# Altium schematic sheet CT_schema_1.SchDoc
size 515 x 463 mm
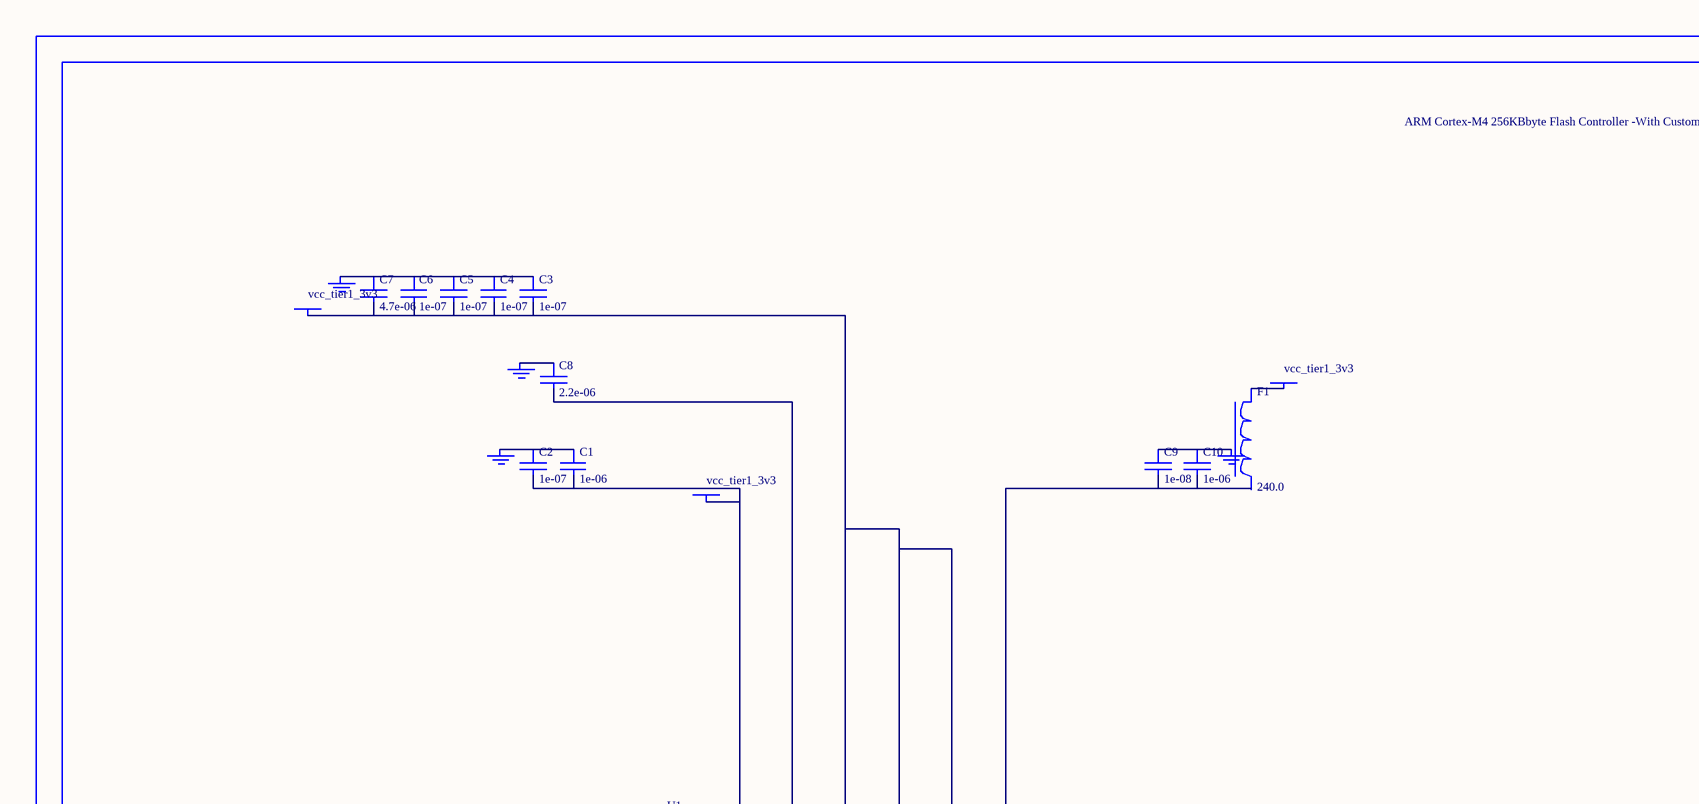
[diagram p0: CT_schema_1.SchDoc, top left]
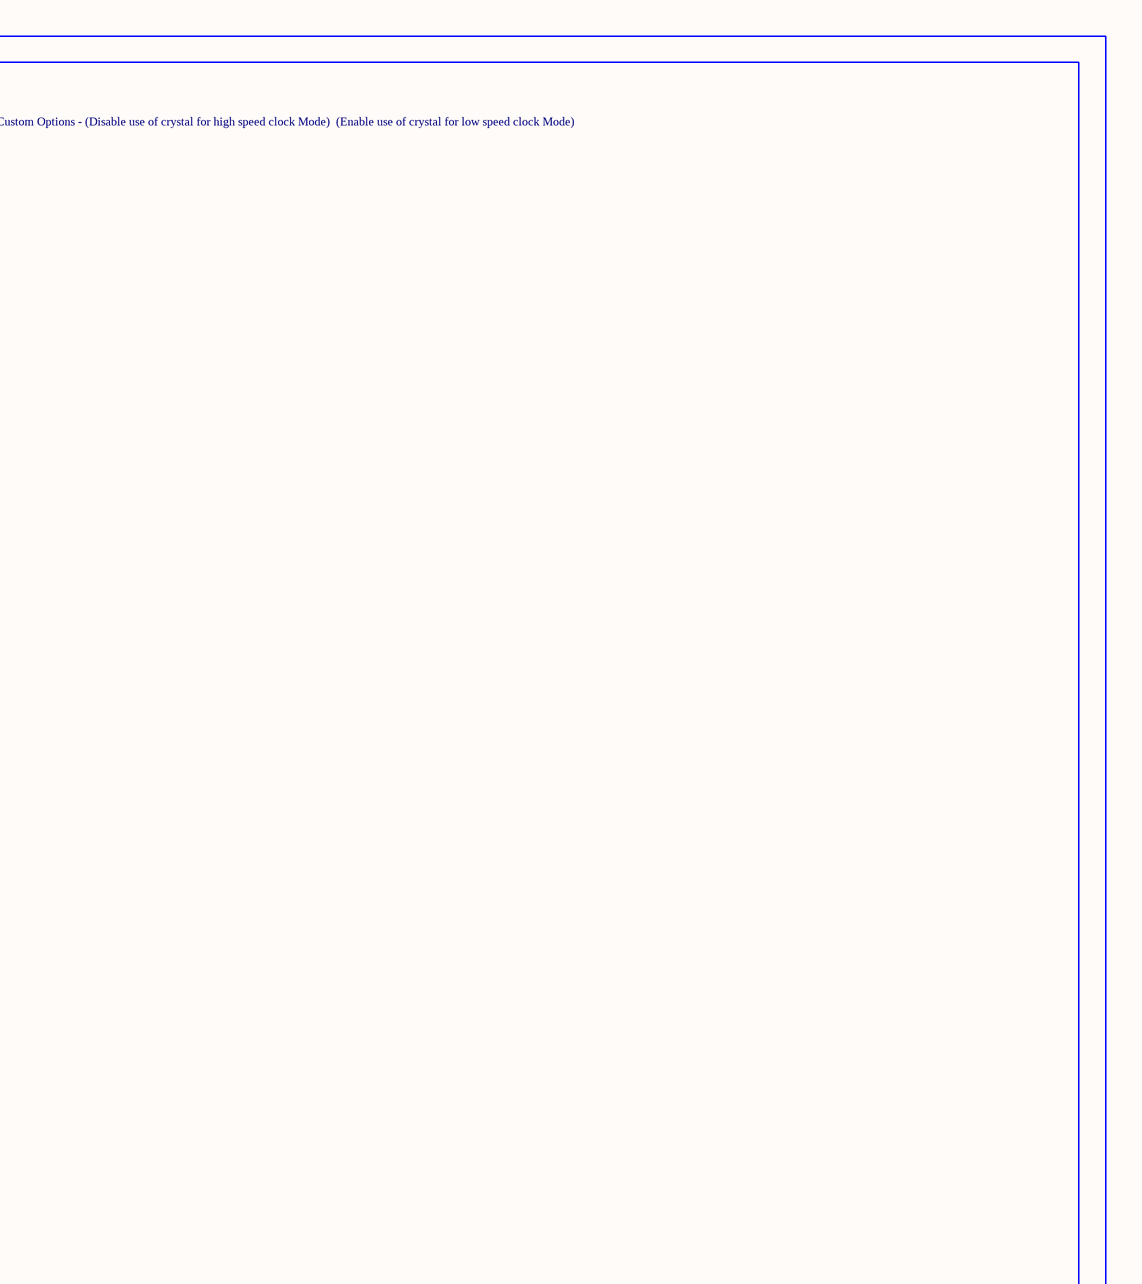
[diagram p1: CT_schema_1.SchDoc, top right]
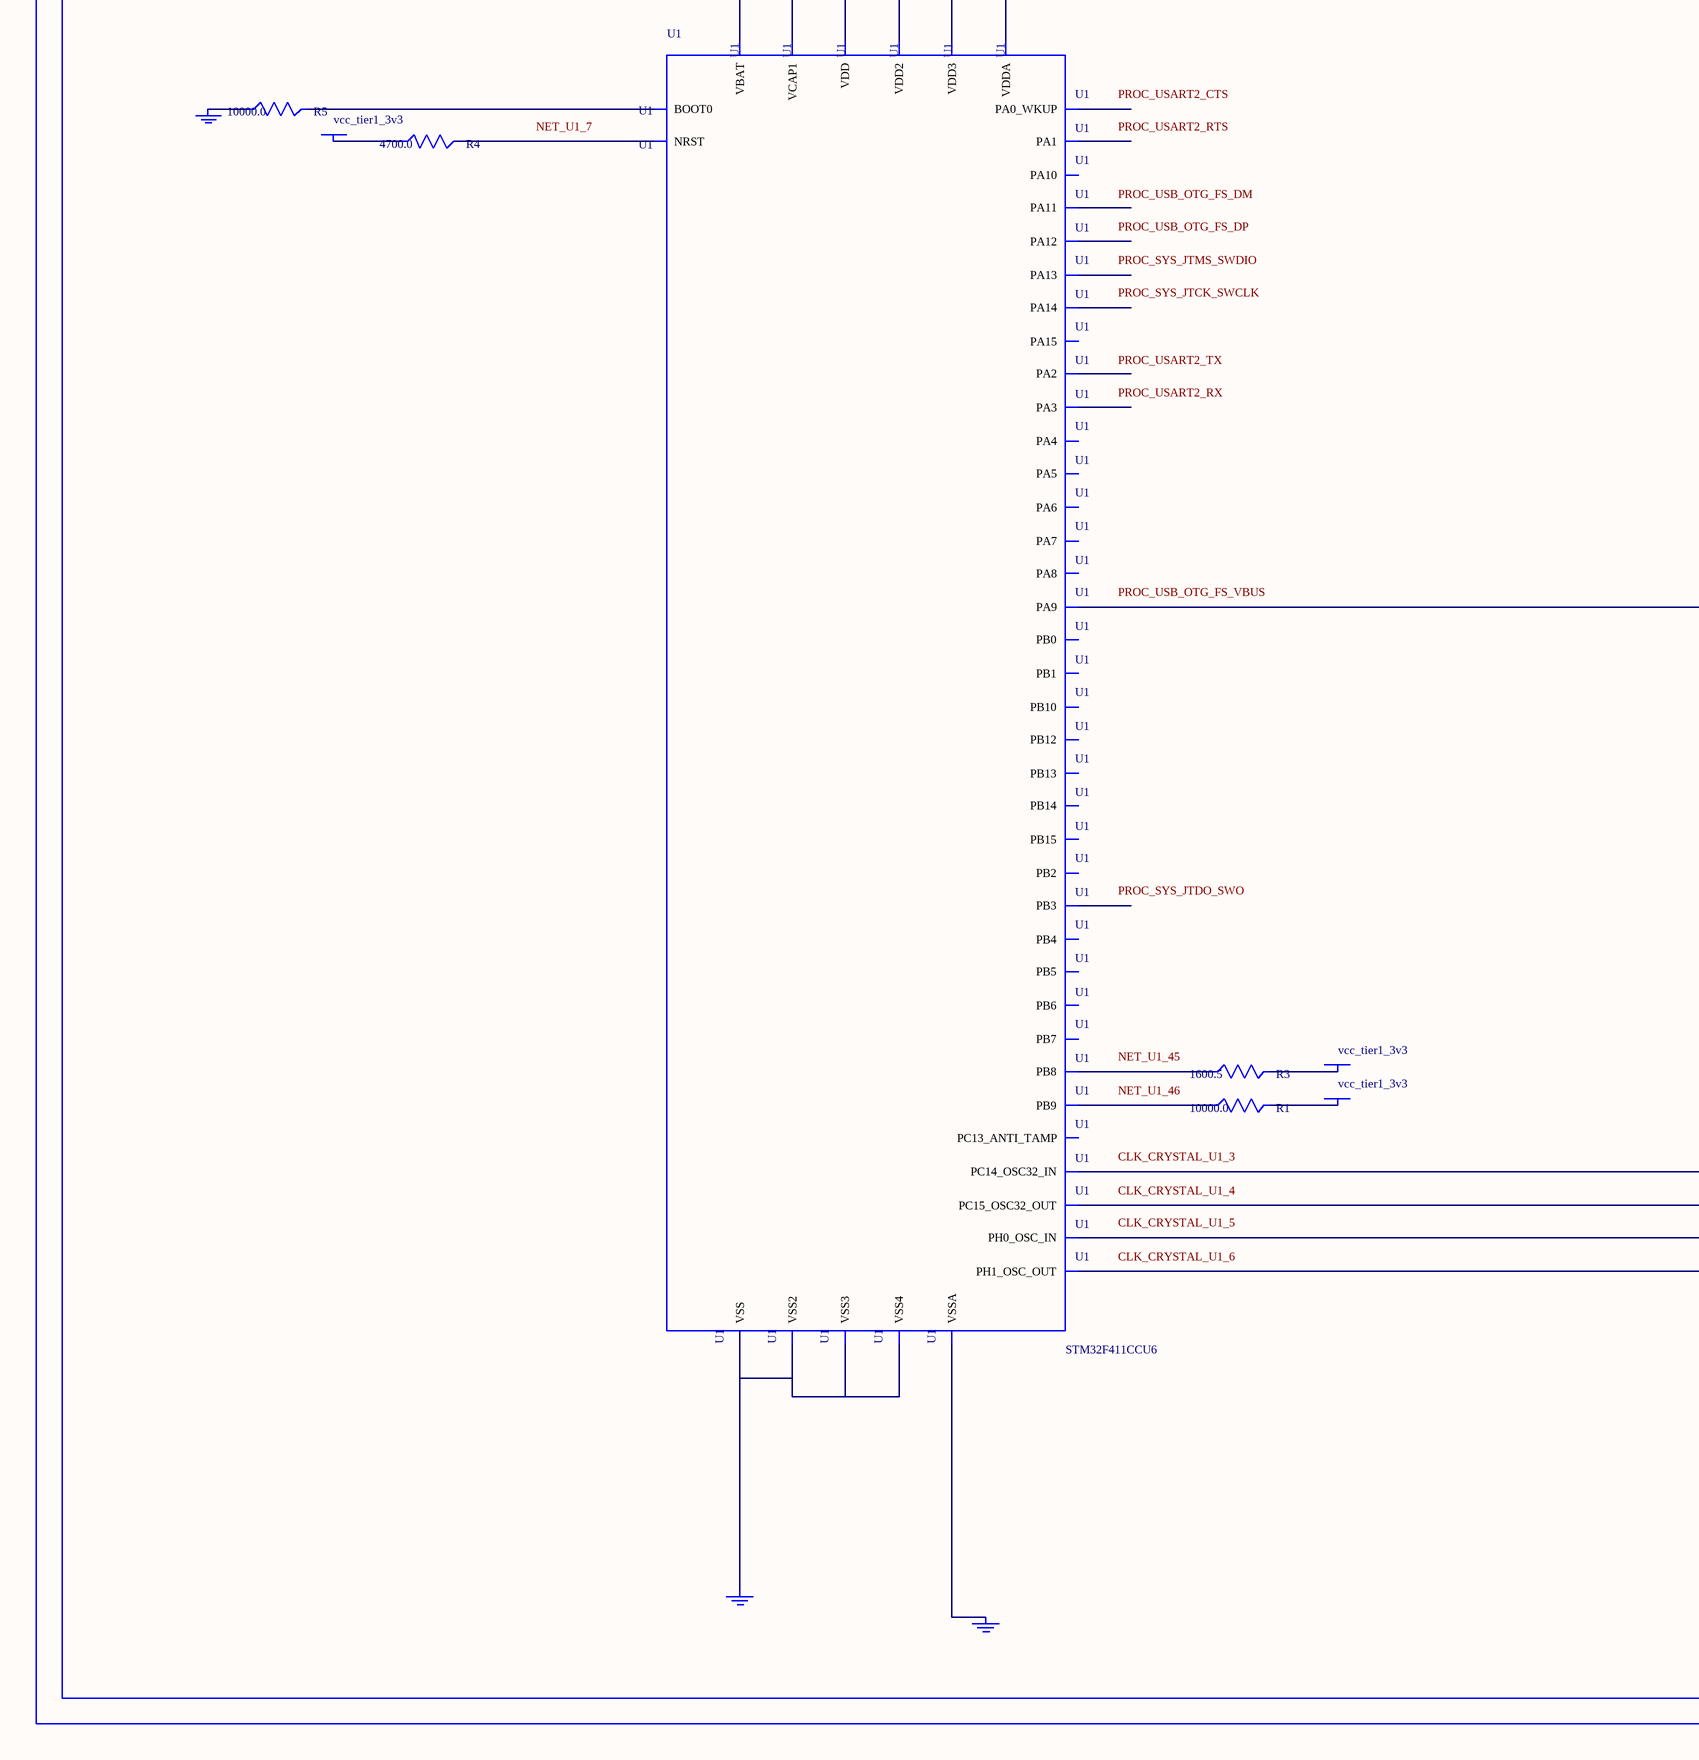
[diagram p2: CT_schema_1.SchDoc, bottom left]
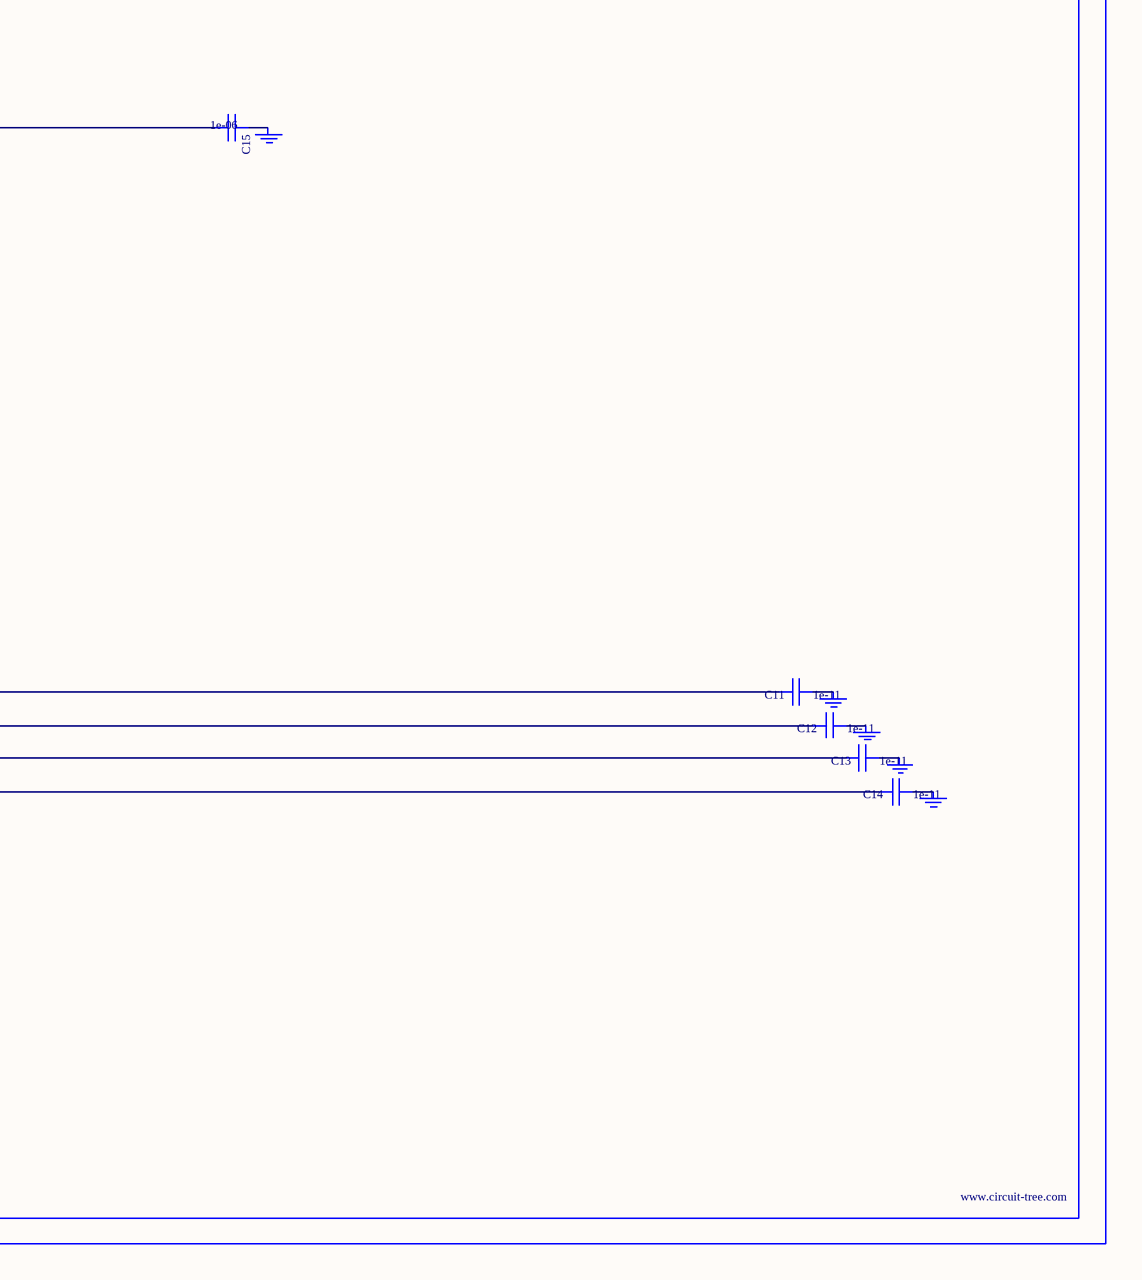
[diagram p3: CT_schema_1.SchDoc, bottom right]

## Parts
BORDER0  (no value)
C1  1e-06  [C0603]
C2  1e-07  [C0603]
C3  1e-07  [C0603]
C4  1e-07  [C0603]
C5  1e-07  [C0603]
C6  1e-07  [C0603]
C7  4.7e-06  [C0603]
C8  2.2e-06  [C0603]
C9  1e-08  [C0603]
C10  1e-06  [C0603]
C11  1e-11  [C0402]
C12  1e-11  [C0402]
C13  1e-11  [C0402]
C14  1e-11  [C0402]
C15  1e-06  [C0603]
F1  240.0  [L0603]
GND_INSTANCE_0_0  (no value)
GND_INSTANCE_0_1  (no value)
GND_INSTANCE_0_2  (no value)
GND_INSTANCE_0_3  (no value)
GND_INSTANCE_0_4  (no value)
GND_INSTANCE_0_5  (no value)
GND_INSTANCE_0_6  (no value)
GND_INSTANCE_0_7  (no value)
GND_INSTANCE_0_8  (no value)
GND_INSTANCE_0_9  (no value)
GND_INSTANCE_0_10  (no value)
GND_INSTANCE_0_11  (no value)
POWER_INSTANCE_0_0  vcc_tier1_3v3
POWER_INSTANCE_0_1  vcc_tier1_3v3
POWER_INSTANCE_0_2  vcc_tier1_3v3
POWER_INSTANCE_0_3  vcc_tier1_3v3
POWER_INSTANCE_0_4  vcc_tier1_3v3
POWER_INSTANCE_0_5  vcc_tier1_3v3
R1  10000.0  [R0603]
R3  1600.5  [R0603]
R4  4700.0  [R0603]
R5  10000.0  [R0603]
U1  STM32F411CCU6  [UFQFPN48]

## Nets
NetC1_1: C1.1 C2.1 GND_INSTANCE_0_0.0(GND)
NetC1_2: C1.2 C2.2 POWER_INSTANCE_0_0.0(PWR) U1.1(VBAT)
NetC3_1: C3.1 C4.1 C5.1 C6.1 C7.1 GND_INSTANCE_0_8.0(GND)
NetC3_2: C3.2 C4.2 C5.2 C6.2 C7.2 POWER_INSTANCE_0_2.0(PWR) U1.24(VDD) U1.36(VDD2) U1.48(VDD3)
NetC8_1: C8.1 GND_INSTANCE_0_7.0(GND)
NetC8_2: C8.2 U1.22(VCAP1)
NetC9_1: C9.1 C10.1 GND_INSTANCE_0_6.0(GND)
NetC9_2: C9.2 C10.2 U1.9(VDDA)
NetC11_1: C11.1 GND_INSTANCE_0_1.0(GND)
NetC11_2: C11.2 U1.3(PC14_OSC32_IN)
NetC12_1: C12.1 GND_INSTANCE_0_2.0(GND)
NetC12_2: C12.2 U1.4(PC15_OSC32_OUT)
NetC13_1: C13.1 GND_INSTANCE_0_3.0(GND)
NetC13_2: C13.2 U1.5(PH0_OSC_IN)
NetC14_1: C14.1 GND_INSTANCE_0_4.0(GND)
NetC14_2: C14.2 U1.6(PH1_OSC_OUT)
NetC15_1: C15.1 GND_INSTANCE_0_9.0(GND)
NetC15_2: C15.2 U1.30(PA9)
NetF1_1: F1.1 POWER_INSTANCE_0_1.0(PWR)
NetGND_INSTANCE_0_5_0: GND_INSTANCE_0_5.0(GND) U1.8(VSSA)
NetGND_INSTANCE_0_10_0: GND_INSTANCE_0_10.0(GND) R5.1
NetGND_INSTANCE_0_11_0: GND_INSTANCE_0_11.0(GND) U1.23(VSS) U1.35(VSS2) U1.47(VSS3) U1.49(VSS4)
NetPOWER_INSTANCE_0_3_0: POWER_INSTANCE_0_3.0(PWR) R4.1
NetPOWER_INSTANCE_0_4_0: POWER_INSTANCE_0_4.0(PWR) R3.2
NetPOWER_INSTANCE_0_5_0: POWER_INSTANCE_0_5.0(PWR) R1.2
NetR1_1: R1.1 U1.46(PB9)
NetR3_1: R3.1 U1.45(PB8)
NetR4_2: R4.2 U1.7(NRST)
NetR5_2: R5.2 U1.44(BOOT0)

Not connected (* = marked no-connect by the designer): F1 2; U1 2(PC13_ANTI_TAMP) 10(PA0_WKUP) 11(PA1) 12(PA2) 13(PA3) 14(PA4) 15(PA5) 16(PA6) 17(PA7) 18(PB0) 19(PB1) 20(PB2) 21(PB10) 25(PB12) 26(PB13) 27(PB14) 28(PB15) 29(PA8) 31(PA10) 32(PA11) 33(PA12) 34(PA13) 37(PA14) 38(PA15) 39(PB3) 40(PB4) 41(PB5) 42(PB6) 43(PB7)

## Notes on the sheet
- Labels drawn without touching a wire or pin: CLK_CRYSTAL_U1_3, CLK_CRYSTAL_U1_4, CLK_CRYSTAL_U1_5, CLK_CRYSTAL_U1_6, NET_U1_7, NET_U1_45, NET_U1_46, PROC_SYS_JTCK_SWCLK, PROC_SYS_JTDO_SWO, PROC_SYS_JTMS_SWDIO, PROC_USART2_CTS, PROC_USART2_RTS, PROC_USART2_RX, PROC_USART2_TX, PROC_USB_OTG_FS_DM, PROC_USB_OTG_FS_DP, PROC_USB_OTG_FS_VBUS

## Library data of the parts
BORDER0 = BORDER_PAGE0
C1 C10 C15 = C0603C105K3RACTU
C2-C6 = 06035C104K4Z2A
C7 = GRM188R6YA475KE15D
C8 = C0603C225K8RACTU
C9 = 06035C103K4Z2A
C11-C14 = C0402C100K3GACTU
F1 = Z0603C241ASMST
GND_INSTANCE_0_0-GND_INSTANCE_0_11 = GND
POWER_INSTANCE_0_0-POWER_INSTANCE_0_5 = PWR
R1 R5 = RC0603JR-0710KL
R3 = R3
R4 = RC0603JR-074K7L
